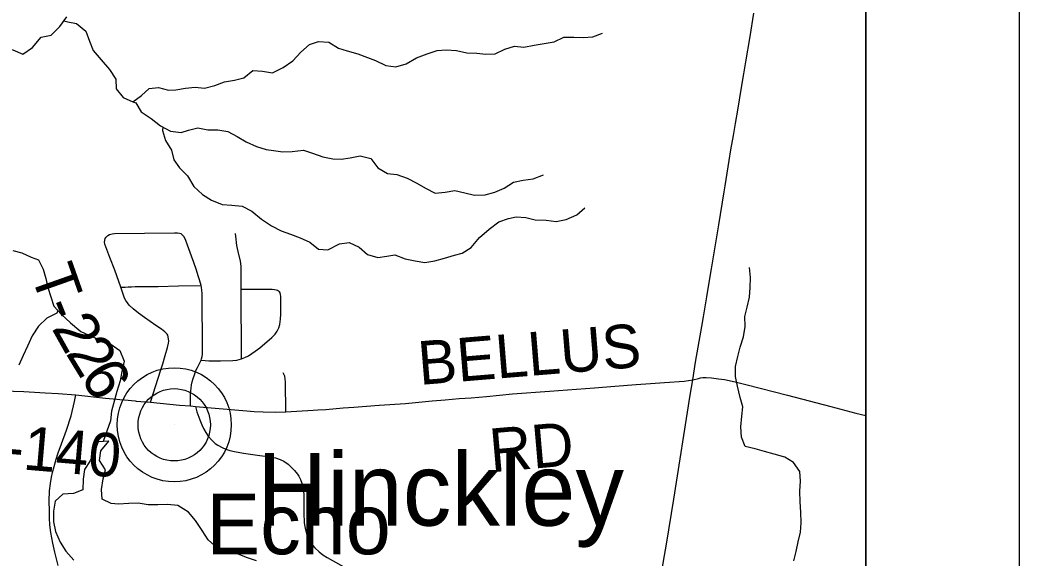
# Model space of a CAD drawing. Extents: x 0 to 34, y 0 to 22.
# Drawn here: x 8.348 to 9, y 18.719 to 19.07 of the extents above; entities that cross this region are included whole.
import ezdxf

# ---------------------------------------------------------------- set-up
doc = ezdxf.new("R2010")
doc.units = 0
for name, color, linetype in [('GM_X_County_Road', 7, 'Continuous'), ('GM_X_County_Road_Text', 7, 'Continuous'), ('GM_X_Major_Lake', 7, 'Continuous'), ('GM_X_Major_Lake_Text', 7, 'Continuous'), ('GM_X_Minor_River', 7, 'Continuous'), ('GM_X_Rail_Line_Text', 7, 'Continuous'), ('GM_X_Township_Road', 7, 'Continuous'), ('GM_X_Township_Road_Text', 7, 'Continuous'), ('GM_X_Unincorporated', 7, 'Continuous'), ('GM_X_Unincorporated_Location', 7, 'Continuous'), ('GM_X_Unincorporated_Text', 7, 'Continuous'), ('SH_Cut_Line', 7, 'Continuous'), ('SH_Data', 7, 'Continuous')]:
    doc.layers.add(name, color=color, linetype=linetype)

msp = doc.modelspace()

# ---------------------------------------------------------------- linework, layer by layer
at = {"layer": 'GM_X_County_Road'}
for points in [[(8.78728, 18.8356), (8.78908, 18.84703), (8.79307, 18.87028), (8.79418, 18.87656), (8.79639, 18.88966), (8.79796, 18.89908), (8.79953, 18.90803), (8.80147, 18.91966), (8.80427, 18.93668), (8.80776, 18.95822), (8.80836, 18.96205), (8.81091, 18.97849), (8.8121, 18.98555), (8.81372, 18.99483), (8.81508, 19.00275), (8.81662, 19.01144), (8.81892, 19.02617), (8.82053, 19.03511), (8.82181, 19.04294), (8.82462, 19.05946), (8.82701, 19.07454)], [(8.4236, 18.82178), (8.42411, 18.82173), (8.43349, 18.82093), (8.45237, 18.81916), (8.45951, 18.81854), (8.46281, 18.81819), (8.49632, 18.8153), (8.50123, 18.81496), (8.50705, 18.81468), (8.51529, 18.81447), (8.52179, 18.81461), (8.53972, 18.81572), (8.54263, 18.81593), (8.54782, 18.81627), (8.55924, 18.81724), (8.56624, 18.81779), (8.58265, 18.81904), (8.5998, 18.8202), (8.61714, 18.82182), (8.62573, 18.82256), (8.63487, 18.8233), (8.64271, 18.82394), (8.65277, 18.82477), (8.66966, 18.82634), (8.69375, 18.82819), (8.7232, 18.8304), (8.7363, 18.83151), (8.75024, 18.83253), (8.75966, 18.83317), (8.7687, 18.83382), (8.78167, 18.8347), (8.78452, 18.83505), (8.78728, 18.8356)], [(8.7532, 18.33871), (8.75587, 18.38615), (8.75633, 18.39547), (8.75744, 18.43572), (8.75864, 18.46562), (8.75883, 18.47042), (8.7604, 18.54436), (8.76076, 18.57491), (8.76095, 18.5906), (8.76215, 18.65577), (8.76243, 18.66629), (8.7628, 18.67404), (8.76354, 18.6818), (8.76418, 18.68743), (8.76686, 18.70884), (8.76806, 18.71724), (8.76999, 18.72841), (8.77489, 18.75786), (8.78559, 18.82551), (8.78728, 18.8356)], [(8.30101, 18.8307), (8.318, 18.82966), (8.3219, 18.8295), (8.34409, 18.8282), (8.35084, 18.82789), (8.36492, 18.82706), (8.37336, 18.82663), (8.38478, 18.82573), (8.40407, 18.82372)], [(8.40407, 18.82372), (8.4115, 18.82294), (8.41355, 18.82275), (8.41646, 18.82247), (8.4236, 18.82178)]]:
    msp.add_lwpolyline(points, dxfattribs=at)
at = {"layer": 'GM_X_Major_Lake'}
for points in [[(8.40632, 18.79564), (8.39939, 18.79513), (8.39695, 18.78884), (8.39413, 18.78274), (8.39054, 18.77701), (8.38963, 18.77073), (8.38947, 18.76389), (8.3832, 18.76157), (8.37636, 18.76097), (8.37124, 18.75657), (8.37014, 18.74991), (8.37017, 18.74306), (8.37153, 18.7366), (8.37461, 18.72977), (8.37826, 18.72389), (8.38361, 18.71802)], [(8.40611, 18.79563), (8.39939, 18.79513), (8.39695, 18.78884), (8.39413, 18.78274), (8.39054, 18.77701), (8.38963, 18.77073), (8.38947, 18.76389), (8.3832, 18.76157), (8.37636, 18.76097), (8.37124, 18.75657), (8.37014, 18.74991), (8.37017, 18.74306), (8.37153, 18.7366), (8.37461, 18.72977), (8.37826, 18.72389), (8.38361, 18.71802)], [(8.40022, 18.78296), (8.40114, 18.78924), (8.40632, 18.79564)], [(8.40022, 18.78296), (8.40114, 18.78924), (8.40624, 18.79554)], [(8.50271, 18.71766), (8.49623, 18.71972), (8.49032, 18.72216), (8.48384, 18.72441), (8.47717, 18.7259), (8.47106, 18.7312), (8.46722, 18.73726), (8.46281, 18.7439), (8.45822, 18.74939), (8.45135, 18.75373), (8.4445, 18.75427), (8.43822, 18.75405), (8.43194, 18.75402), (8.42547, 18.75512), (8.41938, 18.75491), (8.41254, 18.75449), (8.40778, 18.75504), (8.40206, 18.75767), (8.40145, 18.76414), (8.40275, 18.77099), (8.40424, 18.77689), (8.40022, 18.78296)]]:
    msp.add_lwpolyline(points, dxfattribs=at)
at = {"layer": 'GM_X_Minor_River'}
for points in [[(8.33039, 19.05098), (8.33037, 19.05097), (8.33696, 19.05135), (8.34381, 19.05079), (8.35028, 19.04794), (8.35655, 19.05233), (8.36225, 19.05899), (8.36872, 19.06033), (8.37441, 19.06604), (8.37897, 19.07232)], [(8.377, 19.0696), (8.37955, 19.06909), (8.38526, 19.06795), (8.39135, 19.06283), (8.39383, 19.05637), (8.39613, 19.05028), (8.40127, 19.0442), (8.4068, 19.03794), (8.41099, 19.03167), (8.41119, 19.0252), (8.41577, 19.01969), (8.42205, 19.01685), (8.42756, 19.02104), (8.43269, 19.02542), (8.43878, 19.02619), (8.44525, 19.02448), (8.45, 19.02468), (8.45628, 19.02583), (8.46275, 19.02641), (8.46865, 19.02584), (8.47549, 19.02756), (8.48177, 19.02985), (8.48824, 19.031), (8.49432, 19.03253), (8.50021, 19.03729), (8.50649, 19.03692), (8.51315, 19.03579), (8.51999, 19.03922), (8.52627, 19.0436), (8.53159, 19.04912), (8.53729, 19.05426), (8.54318, 19.05617), (8.54984, 19.0558), (8.55612, 19.05181), (8.56183, 19.05011), (8.56869, 19.04822), (8.57497, 19.04575), (8.5803, 19.04386), (8.58696, 19.04044), (8.59343, 19.03969), (8.60028, 19.0416), (8.60712, 19.0456), (8.61397, 19.04808), (8.62043, 19.05037), (8.62633, 19.05076), (8.63318, 19.0502), (8.63984, 19.04868), (8.64631, 19.0485), (8.65221, 19.04794), (8.65829, 19.04814), (8.66457, 19.05119), (8.67084, 19.0531), (8.67693, 19.05253), (8.68378, 19.05368), (8.69671, 19.05598), (8.70318, 19.05903), (8.70965, 19.05904), (8.71574, 19.05886), (8.72201, 19.05925), (8.72829, 19.06154)], [(8.42205, 19.01686), (8.42395, 19.01628), (8.42739, 19.0102), (8.43405, 19.00602), (8.44014, 19.00128), (8.44662, 18.99767), (8.45347, 18.99673), (8.45822, 18.99826), (8.46431, 18.99979), (8.47097, 18.99865), (8.47744, 18.99847), (8.48391, 18.99753), (8.49, 18.9943), (8.4959, 18.9907), (8.50257, 18.98766), (8.50904, 18.98577), (8.5138, 18.9852), (8.51989, 18.98426), (8.52597, 18.98446), (8.5332, 18.98523), (8.5391, 18.98334), (8.54595, 18.98106), (8.55242, 18.97974), (8.55794, 18.97936), (8.56365, 18.98032), (8.5703, 18.98166), (8.57716, 18.97996), (8.58173, 18.97369), (8.58801, 18.97008), (8.5941, 18.96952), (8.60096, 18.96706), (8.60724, 18.96383), (8.61295, 18.96061), (8.61923, 18.95719), (8.6257, 18.95796), (8.63198, 18.95892), (8.63864, 18.95741), (8.64492, 18.95589), (8.65177, 18.95628), (8.65804, 18.958), (8.66413, 18.96048), (8.67021, 18.96448), (8.67668, 18.96582), (8.68314, 18.96659), (8.6898, 18.96926)], [(8.44146, 19.00055), (8.44129, 18.99805), (8.44339, 18.99158), (8.44721, 18.98531), (8.44874, 18.97904), (8.45236, 18.97372), (8.4577, 18.96859), (8.4617, 18.96156), (8.46742, 18.95643), (8.47332, 18.95264), (8.48017, 18.94998), (8.48664, 18.94942), (8.4933, 18.94886), (8.49958, 18.94544), (8.50587, 18.94032), (8.51253, 18.93595), (8.51882, 18.93273), (8.52491, 18.93064), (8.53119, 18.92818), (8.53747, 18.92533), (8.54319, 18.92078), (8.54928, 18.92041), (8.55688, 18.92422), (8.56316, 18.92518), (8.56963, 18.92214), (8.57515, 18.91739), (8.58182, 18.91531), (8.58771, 18.91627), (8.59285, 18.91704), (8.5997, 18.91457), (8.60617, 18.91306), (8.61245, 18.91212), (8.61892, 18.91308), (8.62519, 18.91499), (8.63185, 18.91689), (8.63679, 18.91823), (8.64269, 18.92185), (8.64819, 18.92833), (8.65446, 18.93385), (8.66074, 18.93861), (8.66701, 18.94071), (8.67196, 18.94186), (8.67842, 18.94148), (8.68451, 18.93997), (8.69156, 18.9396), (8.69802, 18.93885), (8.70468, 18.94), (8.71153, 18.94305), (8.71685, 18.94762)], [(8.34362, 18.91996), (8.34952, 18.91844), (8.35561, 18.9156), (8.36056, 18.91389), (8.36342, 18.90781), (8.36514, 18.90173), (8.36648, 18.89584), (8.36858, 18.88975), (8.37049, 18.88367), (8.37545, 18.87816), (8.38135, 18.87266), (8.38802, 18.86715), (8.39487, 18.86412), (8.40097, 18.86146), (8.40706, 18.85919), (8.41353, 18.85463), (8.4164, 18.84779)], [(8.85302, 18.71751), (8.85472, 18.7236), (8.85604, 18.72987), (8.85737, 18.73634), (8.85793, 18.74243), (8.85773, 18.74927), (8.85734, 18.75612), (8.85714, 18.76296), (8.85751, 18.76943), (8.85712, 18.77589), (8.85292, 18.78159), (8.84721, 18.7852), (8.84036, 18.78709), (8.83408, 18.7888), (8.82799, 18.7905), (8.82133, 18.79201), (8.81904, 18.79809), (8.81865, 18.80494), (8.81921, 18.81178), (8.81996, 18.81787), (8.81805, 18.82414), (8.81633, 18.83137), (8.81517, 18.83764), (8.81517, 18.8443), (8.81649, 18.85076), (8.81819, 18.85685), (8.82027, 18.86351), (8.8214, 18.87036), (8.82121, 18.87682), (8.82272, 18.88291), (8.82423, 18.88937), (8.8246, 18.89584), (8.82478, 18.90231), (8.8242, 18.90877)], [(8.37301, 18.88088), (8.3724, 18.87911), (8.36594, 18.87568), (8.36043, 18.87054), (8.35644, 18.86426), (8.35322, 18.8576), (8.35056, 18.85151), (8.34772, 18.84504)], [(8.4164, 18.84779), (8.41488, 18.84094), (8.41375, 18.83485), (8.41148, 18.82801), (8.40807, 18.81507), (8.40751, 18.8088), (8.40271, 18.7954)]]:
    msp.add_lwpolyline(points, dxfattribs=at)
at = {"layer": 'GM_X_Rail_Line_Text'}
msp.add_lwpolyline([(6.96766, 17.90085), (7.25546, 17.90618), (7.40725, 17.90951), (7.5577, 17.91222), (7.69251, 17.91437), (7.76198, 17.91718), (8.01133, 17.91891), (8.70657, 17.92895), (8.9, 17.93196), (8.9, 20.52117)], dxfattribs=at)
at = {"layer": 'GM_X_Township_Road'}
for points in [[(8.4047, 18.92861), (8.40559, 18.92957), (8.40679, 18.93038), (8.40841, 18.93087), (8.4101, 18.93103), (8.4491, 18.93149), (8.45116, 18.93142), (8.45238, 18.93122), (8.45327, 18.93088)], [(8.45951, 18.81854), (8.45969, 18.82659), (8.45999, 18.8301), (8.46023, 18.83227), (8.46059, 18.83421), (8.46132, 18.83651), (8.46211, 18.83887), (8.46319, 18.84159), (8.46416, 18.84359), (8.46531, 18.84583), (8.46664, 18.84836), (8.46688, 18.84927), (8.46713, 18.85078), (8.46737, 18.85236), (8.46749, 18.85423), (8.46713, 18.89186), (8.46695, 18.89398), (8.46676, 18.89579), (8.46652, 18.89706), (8.46537, 18.90087), (8.46465, 18.90341), (8.46344, 18.9071), (8.46172, 18.91202), (8.46023, 18.91612), (8.45763, 18.92338), (8.45648, 18.92646), (8.45545, 18.9287), (8.45491, 18.92955), (8.45406, 18.93039), (8.45327, 18.93088)], [(8.49289, 18.84921), (8.49271, 18.89476), (8.49266, 18.90644), (8.49259, 18.90964), (8.49217, 18.91303), (8.49072, 18.91932), (8.48987, 18.92313), (8.48957, 18.92519), (8.48933, 18.92725), (8.4889, 18.93094)], [(8.43349, 18.82093), (8.4402, 18.84206), (8.44148, 18.8461), (8.44309, 18.85133), (8.4447, 18.85658), (8.44527, 18.85941), (8.44543, 18.86078), (8.44511, 18.86368), (8.44479, 18.86473), (8.44444, 18.8653), (8.44384, 18.86597), (8.44277, 18.86691), (8.44059, 18.86852), (8.43691, 18.87107), (8.42962, 18.87626), (8.42559, 18.87908), (8.4222, 18.88191), (8.41954, 18.88433), (8.41841, 18.88578), (8.41744, 18.88731), (8.41664, 18.88892), (8.41599, 18.8907), (8.41526, 18.89271), (8.4142, 18.89591), (8.41035, 18.90715), (8.40704, 18.91538), (8.4043, 18.92232), (8.40381, 18.92393), (8.40357, 18.9253), (8.40405, 18.92764), (8.4047, 18.92861)], [(8.4142, 18.89591), (8.4171, 18.89606), (8.41891, 18.89615), (8.42109, 18.89627), (8.42351, 18.89633), (8.43845, 18.89652), (8.4517, 18.89682), (8.46652, 18.89706)], [(8.46664, 18.84836), (8.46924, 18.84818), (8.47148, 18.84806), (8.47469, 18.848), (8.47917, 18.84794), (8.48727, 18.84812), (8.48981, 18.84843), (8.49132, 18.84873), (8.49289, 18.84921), (8.49507, 18.85006), (8.49737, 18.85121), (8.49967, 18.85266), (8.50175, 18.85416), (8.50481, 18.85647), (8.51274, 18.86325), (8.51479, 18.86542), (8.51619, 18.86736), (8.51722, 18.86954), (8.51788, 18.87159), (8.51818, 18.87341), (8.51836, 18.87516), (8.51854, 18.87831), (8.5186, 18.88273), (8.51854, 18.88986), (8.51836, 18.89113), (8.518, 18.89228), (8.51758, 18.89301), (8.51709, 18.89361)], [(8.49271, 18.89476), (8.51292, 18.89458), (8.51449, 18.89452), (8.5154, 18.89434), (8.51637, 18.89404), (8.51709, 18.89361)], [(8.52179, 18.81461), (8.52155, 18.83413), (8.52145, 18.83621), (8.52117, 18.83787), (8.52069, 18.83894), (8.52013, 18.84015)], [(8.78728, 18.8356), (8.79089, 18.83651), (8.79224, 18.83686), (8.79379, 18.83701), (8.79603, 18.83707), (8.79953, 18.83677), (8.8039, 18.83625), (8.80795, 18.83571), (8.81476, 18.83428), (8.82189, 18.83259), (8.84907, 18.82558), (8.87723, 18.81818), (8.89363, 18.81391), (8.9, 18.81222)], [(8.37332, 18.71444), (8.37106, 18.72317), (8.36974, 18.72909), (8.36849, 18.73603), (8.36795, 18.74109), (8.36771, 18.74538), (8.36763, 18.75006), (8.36748, 18.75653), (8.36771, 18.76323), (8.36833, 18.76806), (8.36904, 18.77211), (8.36966, 18.77507), (8.37069, 18.77906), (8.37192, 18.7838), (8.37332, 18.78793), (8.37551, 18.79394), (8.37878, 18.80274), (8.38182, 18.81202), (8.384, 18.82152), (8.38478, 18.82573)], [(8.46281, 18.81819), (8.46383, 18.8148), (8.46567, 18.80954), (8.46697, 18.80631), (8.46807, 18.80382), (8.46964, 18.80124), (8.47121, 18.79893), (8.47361, 18.79616), (8.47574, 18.79413), (8.47752, 18.79289), (8.48017, 18.79145), (8.48256, 18.79044), (8.48533, 18.78951), (8.48829, 18.78887), (8.4941, 18.78785), (8.50481, 18.78628), (8.51173, 18.78527), (8.51496, 18.78462), (8.51801, 18.7837), (8.5205, 18.78259), (8.52336, 18.78056), (8.52558, 18.77844), (8.52742, 18.7765), (8.52936, 18.7741), (8.53024, 18.77272), (8.53139, 18.77059), (8.53231, 18.76819), (8.53296, 18.76524), (8.53342, 18.76099), (8.53361, 18.74881), (8.53379, 18.74226), (8.53407, 18.74004), (8.53453, 18.73773), (8.53527, 18.73515), (8.53647, 18.73247), (8.53822, 18.72933), (8.53924, 18.72776), (8.54062, 18.7261), (8.54348, 18.72333), (8.54598, 18.72149), (8.54875, 18.71973), (8.57394, 18.70561)]]:
    msp.add_lwpolyline(points, dxfattribs=at)
at = {"layer": 'GM_X_Unincorporated'}
for radius in [0.0372, 0.02358]:
    msp.add_circle((8.44899, 18.80625), radius, dxfattribs=at)
at = {"layer": 'GM_X_Unincorporated_Location'}
msp.add_line((8.44899, 18.80625), (8.44899, 18.80625), dxfattribs=at)
at = {"layer": 'SH_Cut_Line'}
msp.add_lwpolyline([(2.1, 14.1), (8.9, 14.1), (8.9, 20.52117), (8.88492, 20.52095), (8.78844, 20.51908), (8.45204, 20.51253), (8.41696, 20.51215), (8.39386, 20.51177), (8.38319, 20.51123), (8.37874, 20.51114), (8.37504, 20.51102), (8.18847, 20.50622), (7.95771, 20.5026), (7.74412, 20.50184), (7.55552, 20.49834), (7.41076, 20.49536), (7.12851, 20.48984), (7.05001, 20.48828), (6.99108, 20.48711)], dxfattribs=at)
at = {"layer": 'SH_Data'}
for p, q in [((9, 21), (9, 14)), ((8.9, 20.9), (8.9, 14.1))]:
    msp.add_line(p, q, dxfattribs=at)

# ---------------------------------------------------------------- texts
at = {"layer": 'GM_X_County_Road_Text'}
for s, rotation, p in [('BELLUS', 4.704, (8.60913, 18.83221)), ('C-140', 355.1012, (8.30994, 18.7806)), ('RD', 4.96901, (8.65583, 18.77528))]:
    msp.add_text(s, height=0.028409, rotation=rotation, dxfattribs=at).set_placement(p)
at = {"layer": 'GM_X_Major_Lake_Text'}
msp.add_text('Hinckley', height=0.047372, rotation=359.98279, dxfattribs=at).set_placement((8.50299, 18.74054))
at = {"layer": 'GM_X_Township_Road_Text'}
for s, rotation, p in [('T', 289.44598, (8.35509, 18.90498)), ('-', 291.86043, (8.36262, 18.88372)), ('2', 299.32328, (8.36871, 18.86925)), ('2', 301.41056, (8.37785, 18.85302)), ('6', 301.56136, (8.38701, 18.83802))]:
    msp.add_text(s, height=0.02841, rotation=rotation, dxfattribs=at).set_placement(p)
at = {"layer": 'GM_X_Unincorporated_Text'}
msp.add_text('Echo', height=0.039489, rotation=0.00001, dxfattribs=at).set_placement((8.46986, 18.72185))

doc.saveas('drawing.dxf')
